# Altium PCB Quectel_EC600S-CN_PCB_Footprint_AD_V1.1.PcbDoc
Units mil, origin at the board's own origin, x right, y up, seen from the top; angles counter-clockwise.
Board outline 6000 x 4000 mil, 2 copper layers (Top Layer, Bottom Layer); 1 components, 0 nets, 92 pads, 0 vias.
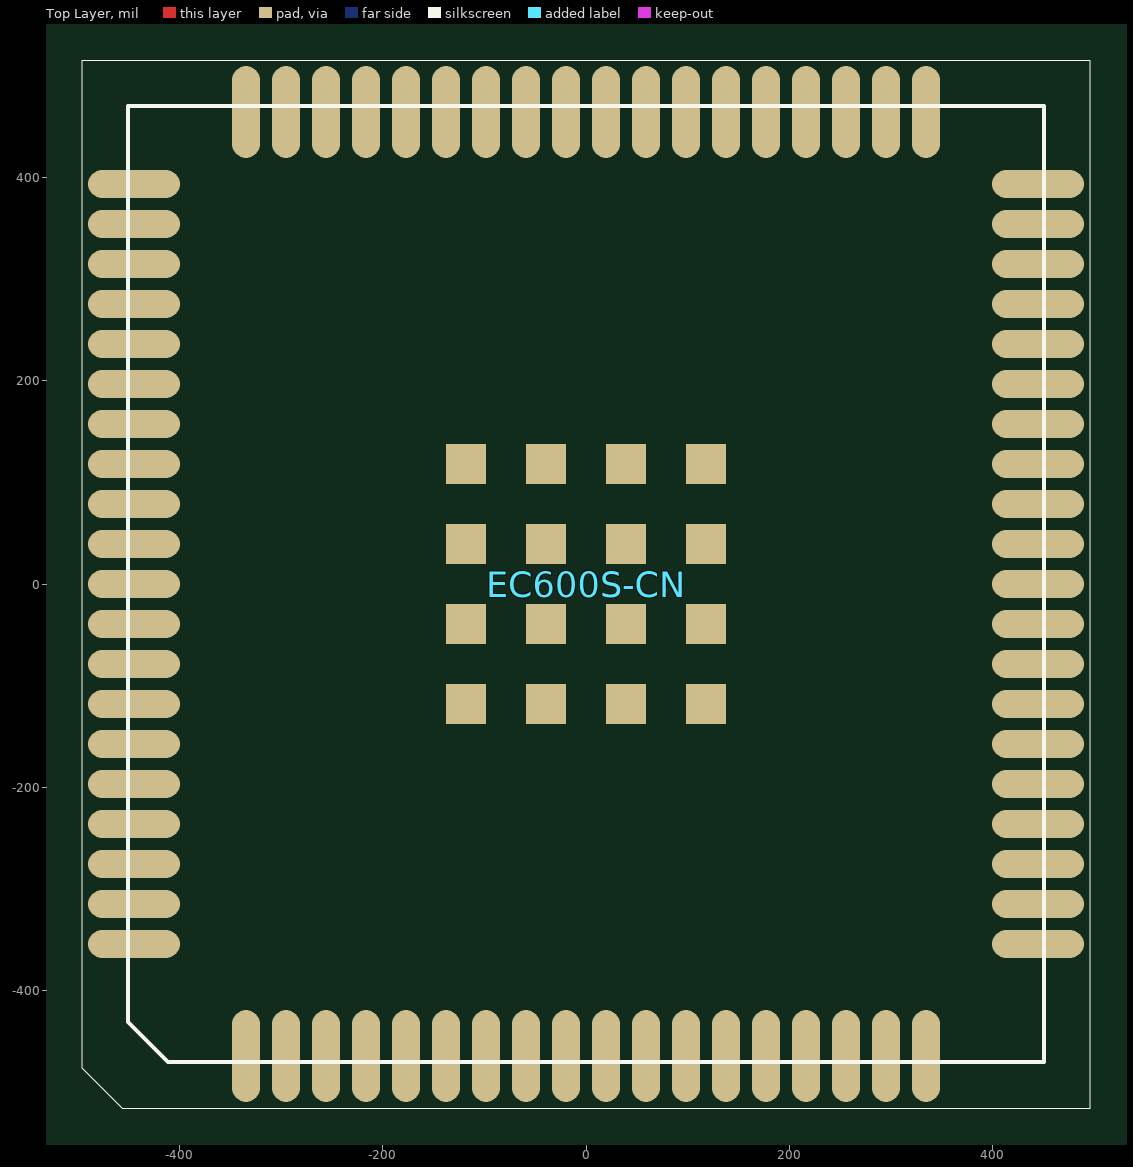
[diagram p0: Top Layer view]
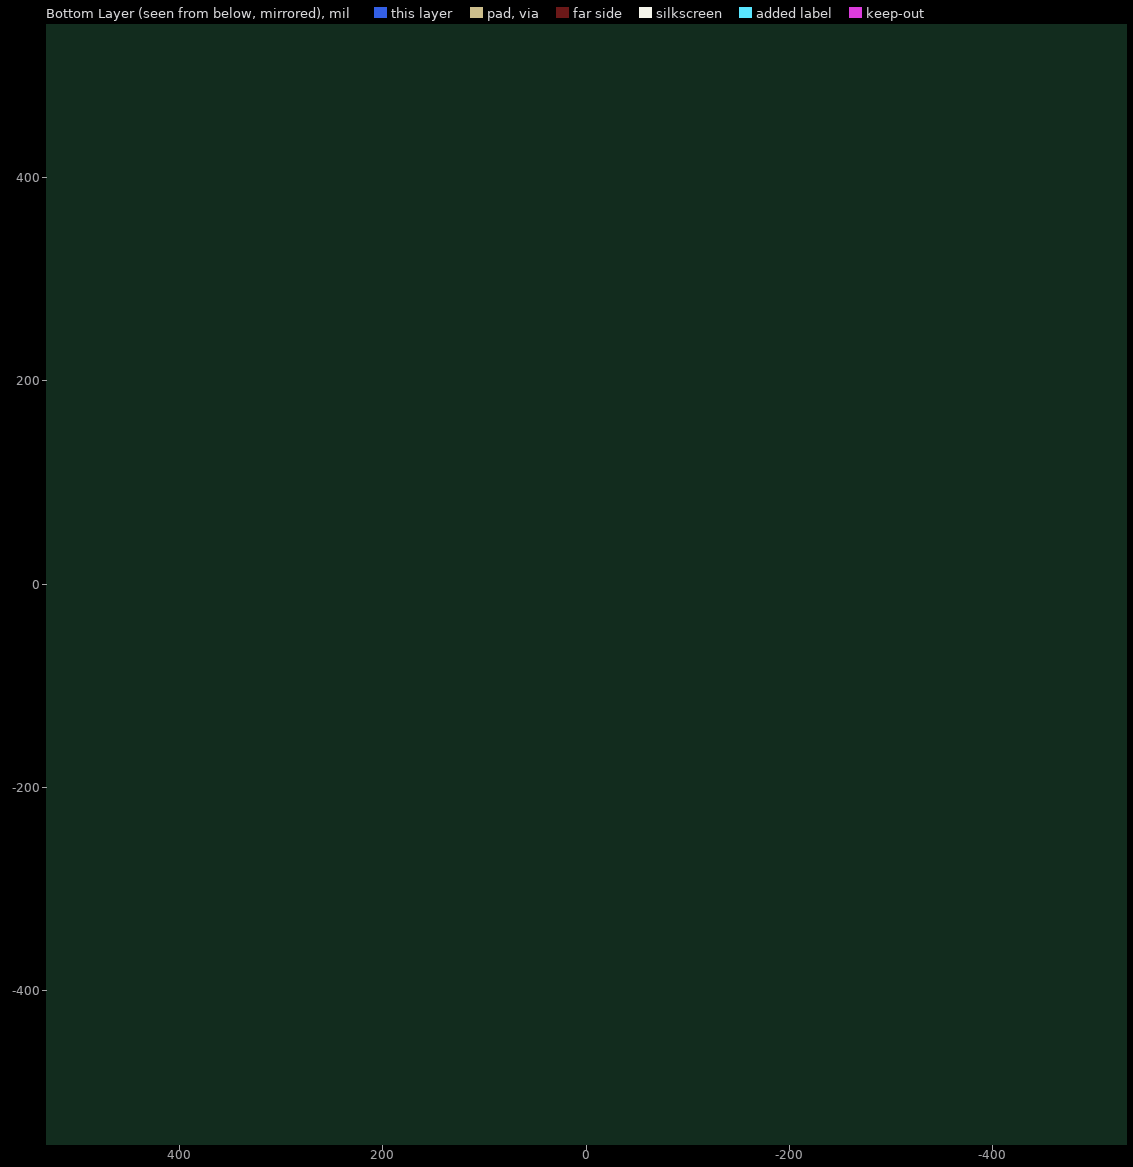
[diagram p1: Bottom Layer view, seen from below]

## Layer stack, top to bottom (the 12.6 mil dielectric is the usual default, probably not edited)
Top Layer: signal copper 1.4
Dielectric: dielectric 12.6, FR-4, Dk 4.8
Bottom Layer: signal copper 1.4

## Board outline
-2785,-2115 3215,-2115 3215,1885 -2785,1885

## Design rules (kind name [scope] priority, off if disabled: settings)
Clearance [All] p1: gap=10
PolygonConnect [All] p1: connectstyle=Relief reliefconductorwidth=10 reliefentries=4 polygonreliefangle="90 Angle" airgapwidth=10
RoutingVias [All] p1: holewidth=28 width=50 viastyle="Through Hole" minholewidth=28 minwidth=50 maxholewidth=28 maxwidth=50
SolderMaskExpansion [All] p1: expansion=4
Width [All] p1: maxlimit=10 minlimit=10 preferedwidth=10
28 further rules are at their usual default settings.

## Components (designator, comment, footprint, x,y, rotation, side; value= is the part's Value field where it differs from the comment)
EC600S-CN "Comment" EC600S-CN 0,0 r0 top

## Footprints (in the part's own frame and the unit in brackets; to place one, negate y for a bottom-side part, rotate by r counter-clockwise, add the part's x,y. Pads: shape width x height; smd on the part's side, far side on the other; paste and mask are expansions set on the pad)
EC600S-CN [mm] "EC600S-CN module 76LCC 16LGA 22.9x23.9mm H2.5mm RO"
  oval 0.7x2.3 smd mask+0.05: 1(-8.5,-11.8) 2(-7.5,-11.8) 3(-6.5,-11.8) 4(-5.5,-11.8) 5(-4.5,-11.8) 6(-3.5,-11.8) 7(-2.5,-11.8) 8(-1.5,-11.8) 9(-0.5,-11.8) 10(0.5,-11.8) 11(1.5,-11.8) 12(2.5,-11.8) 13(3.5,-11.8) 14(4.5,-11.8) 15(5.5,-11.8) 16(6.5,-11.8) 17(7.5,-11.8) 18(8.5,-11.8) 39(8.5,11.8) 40(7.5,11.8) 41(6.5,11.8) 42(5.5,11.8) 43(4.5,11.8) 44(3.5,11.8) 45(2.5,11.8) 46(1.5,11.8) 47(0.5,11.8) 48(-0.5,11.8) 49(-1.5,11.8) 50(-2.5,11.8) 51(-3.5,11.8) 52(-4.5,11.8) 53(-5.5,11.8) 54(-6.5,11.8) 55(-7.5,11.8) 56(-8.5,11.8)
  oval 2.3x0.7 smd mask+0.05: 19(11.3,-9) 20(11.3,-8) 21(11.3,-7) 22(11.3,-6) 23(11.3,-5) 24(11.3,-4) 25(11.3,-3) 26(11.3,-2) 27(11.3,-1) 28(11.3,0) 29(11.3,1) 30(11.3,2) 31(11.3,3) 32(11.3,4) 33(11.3,5) 34(11.3,6) 35(11.3,7) 36(11.3,8) 37(11.3,9) 38(11.3,10) 57(-11.3,10) 58(-11.3,9) 59(-11.3,8) 60(-11.3,7) 61(-11.3,6) 62(-11.3,5) 63(-11.3,4) 64(-11.3,3) 65(-11.3,2) 66(-11.3,1) 67(-11.3,0) 68(-11.3,-1) 69(-11.3,-2) 70(-11.3,-3) 71(-11.3,-4) 72(-11.3,-5) 73(-11.3,-6) 74(-11.3,-7) 75(-11.3,-8) 76(-11.3,-9)
  rect 1x1 smd mask+0.05: 77(-3,-3) 78(-1,-3) 79(1,-3) 80(3,-3) 81(3,-1) 82(3,1) 83(3,3) 84(1,3) 85(-1,3) 86(-3,3) 87(-3,1) 88(-3,-1) 89(-1,-1) 90(1,-1) 91(1,1) 92(-1,1)
  silkscreen extent -12.6,-13.1 12.6,13.1

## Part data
EC600S-CN: "EC600S-CN module 76LCC 16LGA 22.9x23.9mm H2.5mm RO"

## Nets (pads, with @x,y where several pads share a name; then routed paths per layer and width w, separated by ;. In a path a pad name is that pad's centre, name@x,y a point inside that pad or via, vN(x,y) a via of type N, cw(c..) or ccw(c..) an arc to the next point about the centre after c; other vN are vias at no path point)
pads on no net: EC600S-CN.1 EC600S-CN.2 EC600S-CN.3 EC600S-CN.4 EC600S-CN.5 EC600S-CN.6 EC600S-CN.7 EC600S-CN.8 EC600S-CN.9 EC600S-CN.10 EC600S-CN.11 EC600S-CN.12 EC600S-CN.13 EC600S-CN.14 EC600S-CN.15 EC600S-CN.16 EC600S-CN.17 EC600S-CN.18 EC600S-CN.19 EC600S-CN.20 EC600S-CN.21 EC600S-CN.22 EC600S-CN.23 EC600S-CN.24 EC600S-CN.25 EC600S-CN.26 EC600S-CN.27 EC600S-CN.28 EC600S-CN.29 EC600S-CN.30 EC600S-CN.31 EC600S-CN.32 EC600S-CN.33 EC600S-CN.34 EC600S-CN.35 EC600S-CN.36 EC600S-CN.37 EC600S-CN.38 EC600S-CN.39 EC600S-CN.40 EC600S-CN.41 EC600S-CN.42 EC600S-CN.43 EC600S-CN.44 EC600S-CN.45 EC600S-CN.46 EC600S-CN.47 EC600S-CN.48 EC600S-CN.49 EC600S-CN.50 EC600S-CN.51 EC600S-CN.52 EC600S-CN.53 EC600S-CN.54 EC600S-CN.55 EC600S-CN.56 EC600S-CN.57 EC600S-CN.58 EC600S-CN.59 EC600S-CN.60 EC600S-CN.61 EC600S-CN.62 EC600S-CN.63 EC600S-CN.64 EC600S-CN.65 EC600S-CN.66 EC600S-CN.67 EC600S-CN.68 EC600S-CN.69 EC600S-CN.70 EC600S-CN.71 EC600S-CN.72 EC600S-CN.73 EC600S-CN.74 EC600S-CN.75 EC600S-CN.76 EC600S-CN.77 EC600S-CN.78 EC600S-CN.79 EC600S-CN.80 EC600S-CN.81 EC600S-CN.82 EC600S-CN.83 EC600S-CN.84 EC600S-CN.85 EC600S-CN.86 EC600S-CN.87 EC600S-CN.88 EC600S-CN.89 EC600S-CN.90 EC600S-CN.91 EC600S-CN.92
